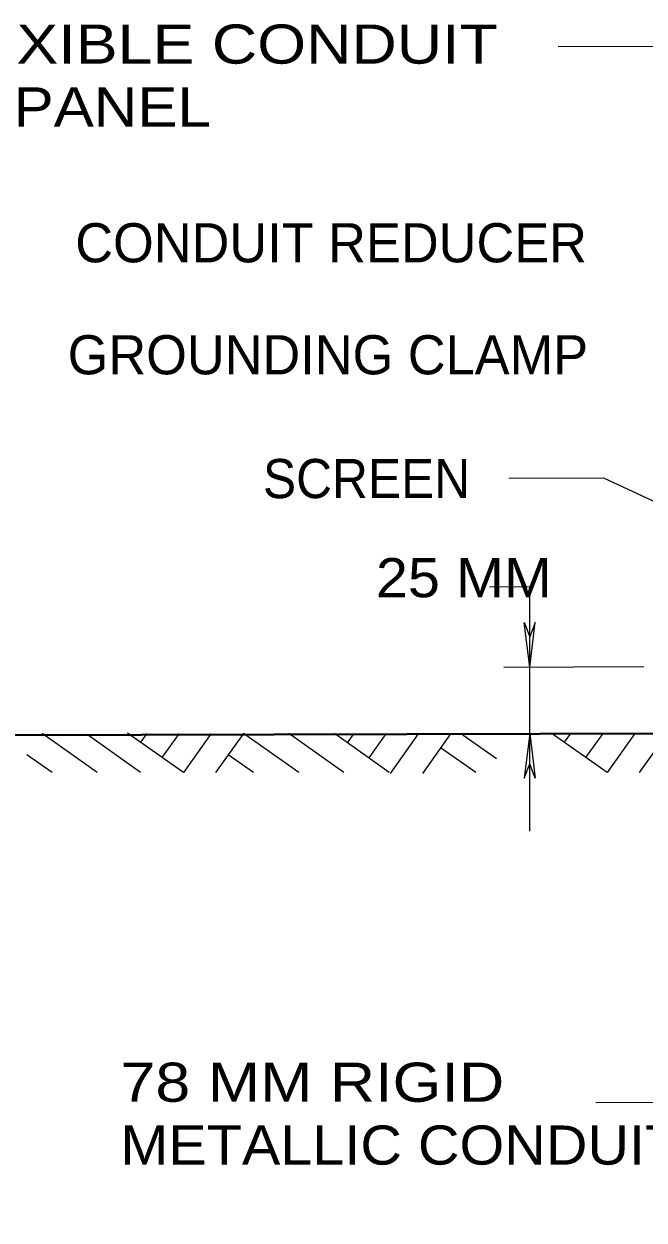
# Model space of a CAD drawing. Extents: x 312583 to 312854, y 144419 to 144597.
# Drawn here: x 312774.81 to 312786.86, y 144462.25 to 144485.47 of the extents above; entities that cross this region are included whole.
import ezdxf

# ---------------------------------------------------------------- set-up
doc = ezdxf.new("R2010")
doc.units = 0
doc.header["$LTSCALE"] = 0.3
doc.layers.add('1', color=7, linetype='Continuous', lineweight=40)
doc.layers.add('2', color=7, linetype='Continuous', lineweight=13)

msp = doc.modelspace()

# ---------------------------------------------------------------- linework, layer by layer
at = {"layer": '1'}
msp.add_line((312787.4365, 144471.6969), (312774.5105, 144471.6662), dxfattribs=at)
at = {"layer": '2'}
for p, q in [((312784.2318, 144476.6496), (312786.0718, 144476.6572)), ((312786.0718, 144476.6572), (312792.8415, 144473.4909)), ((312783.8562, 144474.5412), (312784.6382, 144474.5489)), ((312784.6382, 144472.9849), (312784.6382, 144474.5489)), ((312784.5308, 144473.8512), (312784.6382, 144473.5752)), ((312784.6382, 144472.9849), (312784.5308, 144473.8512)), ((312784.7455, 144473.8512), (312784.6382, 144473.5752)), ((312784.6382, 144472.9849), (312784.7455, 144473.8512)), ((312784.1322, 144472.9849), (312786.8538, 144473.0002)), ((312776.2355, 144470.9379), (312775.1698, 144471.6969)), ((312777.0788, 144470.9379), (312776.0438, 144471.6739)), ((312777.9145, 144470.9379), (312776.8258, 144471.7046)), ((312777.2015, 144471.6969), (312777.0788, 144471.5282)), ((312777.8302, 144471.6969), (312777.4928, 144471.2292)), ((312778.4512, 144471.6969), (312777.9145, 144470.9379)), ((312779.0798, 144471.6969), (312778.5355, 144470.9379)), ((312780.1532, 144470.9379), (312779.0798, 144471.6969)), ((312781.0272, 144470.9379), (312779.9615, 144471.6969)), ((312781.9088, 144470.9379), (312780.8432, 144471.6969)), ((312781.2112, 144471.6892), (312781.0962, 144471.5206)), ((312781.8398, 144471.6892), (312781.5102, 144471.2216)), ((312782.4685, 144471.6892), (312781.9242, 144470.9226)), ((312783.0972, 144471.6892), (312782.5528, 144470.9226)), ((312783.9942, 144471.2062), (312783.3348, 144471.6662)), ((312784.6382, 144471.6969), (312784.5308, 144470.8306)), ((312784.6382, 144471.6969), (312784.7455, 144470.8306)), ((312786.1408, 144470.9379), (312785.0522, 144471.7046)), ((312785.4278, 144471.6969), (312785.3052, 144471.5282)), ((312786.0565, 144471.6969), (312785.7192, 144471.2292)), ((312786.6775, 144471.6969), (312786.1408, 144470.9379)), ((312787.3062, 144471.6969), (312786.7618, 144470.9379)), ((312783.5878, 144470.9379), (312782.9208, 144471.4056)), ((312775.3615, 144470.9379), (312774.8708, 144471.2829)), ((312779.2715, 144470.9379), (312778.7808, 144471.2829)), ((312784.5308, 144470.8306), (312784.6382, 144471.1066)), ((312784.7455, 144470.8306), (312784.6382, 144471.1066))]:
    msp.add_line(p, q, dxfattribs=at)
for points in [[(312785.1902, 144485.0292), (312787.0302, 144485.0369), (312792.4812, 144482.4456)], [(312784.6382, 144469.8032), (312784.6382, 144471.6969), (312784.6382, 144472.9849)], [(312785.9185, 144464.5362), (312791.8372, 144464.5439), (312793.8228, 144462.2516)]]:
    msp.add_lwpolyline(points, dxfattribs=at)

# ---------------------------------------------------------------- texts
for s, width, p in [('3 #8 IN 41 MM FLEXIBLE CONDUIT', 1.2, (312764.0939, 144484.6986)), ('TO DISTRIBUTION PANEL', 1.15, (312764.0939, 144483.4786)), ('SCREEN', 0.95, (312779.4562, 144476.2652)), ('25 MM', 1.1, (312781.6497, 144474.3409)), ('78 MM RIGID', 1.2, (312776.6878, 144464.5476)), ('METALLIC CONDUIT', 1.1, (312776.6878, 144463.3276))]:
    msp.add_text(s, height=0.76, dxfattribs=dict(at, width=width)).set_placement(p)
for s, p in [('CONDUIT REDUCER', (312775.8108, 144480.8422)), ('GROUNDING CLAMP', (312775.663, 144478.6679))]:
    msp.add_text(s, height=0.76, dxfattribs=at).set_placement(p)

doc.saveas('drawing.dxf')
